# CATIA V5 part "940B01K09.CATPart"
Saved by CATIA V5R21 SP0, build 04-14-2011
Part number: 940B01K09
Bounding box of the stored display mesh (mm): x -8.5 to 199.1, y -7 to 7, z -25.901 to 9.099
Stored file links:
  C:\Users\ALI OZGUN\Desktop\alhan\940B01K09.CATPart
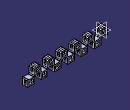
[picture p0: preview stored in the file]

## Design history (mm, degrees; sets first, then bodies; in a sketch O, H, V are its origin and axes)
Body1 (main body)
  Sketch1 on zx-plane, origin (0, 0, 0), H (-1, 0, 0), V (0, 0, 1)
    point P1 (-8.5, -8.9006)
    line L1 (-8.5, -7.9006) -> (-8, -7.4006)
    point P2 (-8, -7.4006)
    line L2 (-8, -7.4006) -> (-8, 6.6246)
    point P3 (-8, 6.6246)
    line L3 (-8, 6.6246) -> (-5.5251, 9.0994)
    point P4 (-5.5251, 9.0994)
    line L4 (-5.5251, 9.0994) -> (0, 9.0994)
    point P5 (0, 9.0994)
    line L5 (-8.5, -7.9006) -> (-8.5, -11.9006)
    point P6 (-8.5, -11.9006)
    line L6 (-8.5, -11.9006) -> (-5, -8.4006)
    point P7 (-3.5, -6.9006)
    line L7 (-5, -6.9006) -> (0, -6.9006)
    point P8 (0, -6.9006)
    line L8 (0, 6.2994) -> (-4.0825, 6.2994)
    point P9 (-4.0825, 6.2994)
    line L9 (-4.0825, 6.2994) -> (-5.2, 5.1819)
    point P10 (-5.2, 5.1819)
    line L10 (-5.2, 5.1819) -> (-5.2, -3.4006)
    point P11 (-5.2, -3.4006)
    line L11 (-5.2, -3.4006) -> (0, -3.4006)
    point P12 (0, -3.4006)
    point P13 (-8.5, -7.9006)
    point P14 (8, -7.4006)
    point P15 (8.5, -7.9006)
    line L12 (8.5, -7.9006) -> (8, -7.4006)
    point P16 (8, 6.6246)
    line L13 (8, -7.4006) -> (8, 6.6246)
    point P17 (5.5251, 9.0994)
    line L14 (8, 6.6246) -> (5.5251, 9.0994)
    point P18 (8.5, -11.9006)
    line L15 (8.5, -7.9006) -> (8.5, -11.9006)
    point P19 (3.5, -6.9006)
    line L16 (8.5, -11.9006) -> (5, -8.4006)
    point P20 (5.2, 5.1819)
    point P21 (4.0825, 6.2994)
    line L17 (4.0825, 6.2994) -> (5.2, 5.1819)
    point P22 (5.2, -3.4006)
    line L18 (5.2, 5.1819) -> (5.2, -3.4006)
    point P23 (0, -6.9006)
    line L19 (5, -6.9006) -> (0, -6.9006)
    point P24 (0, -3.4006)
    line L20 (5.2, -3.4006) -> (0, -3.4006)
    line L21 (0, 6.2994) -> (4.0825, 6.2994)
    point P25 (0, 9.0994)
    line L22 (5.5251, 9.0994) -> (0, 9.0994)
    point P26 (0, 6.2994)
    point P27 (0, 6.2994)
    line L23 (-5, -6.9006) -> (-5, -8.4006)
    line L24 (5, -6.9006) -> (5, -8.4006)
    distance L2 V = 8
    angle L3 L2 = 135
    distance L4 H = 9.0994
    distance L8 L4 = 2.8
    distance L10 L2 = 2.8
    distance L11 L7 = 3.5
    distance L9 L3 = 3
    length L3 = 3.5
    distance L4 L7 = 16
    distance L4 P6 = 21
    distance L5 L2 = 0.5
    length L5 = 4
    distance L23 L2 = 3
    vertical: L2 V, L5 V, L10 V, L23 V
    parallelism: L3 L1, L6 L1
    horizontal: L4 H, L7 H, L8 H, L11 H
    coincidence: P5 V, P8 V, P12 V, P1 L5, P26 V, P27 V, P5 P25, P8 P23, P12 P24, P26 P27, P7 L7, P7 L6, P19 L16, P19 L19
    symmetry: P2 P14 V, P13 P15 V, L1 L12 V, P3 P16 V, L2 L13 V, P4 P17 V, L3 L14 V, P6 P18 V, L5 L15 V, P7 P19 V, L6 L16 V, P10 P20 V, P9 P21 V, L9 L17 V, P11 P22 V, L10 L18 V, P8 P23 V, L7 L19 V, P12 P24 V, L11 L20 V, L8 L21 V, P5 P25 V, L4 L22 V, L23 L24 V
  Pad1: profile Sketch1, direction (0, 1, 0), length 7, mirrored extent
  Fillet1: radius 3, on edge [face of Pad1 from Sketch1.L22 | face of Pad1 from Sketch1.L14]; edge [face of Pad1 from Sketch1.L3 | face of Pad1 from Sketch1.L4]; edge [face of Pad1 from Sketch1.L2 | face of Pad1 from Sketch1.L3]; edge [face of Pad1 from Sketch1.L14 | face of Pad1 from Sketch1.L13]
  Fillet2: radius 1, on edge [face of Pad1 from Sketch1.L17 | face of Pad1 from Sketch1.L21]; edge [face of Pad1 from Sketch1.L18 | face of Pad1 from Sketch1.L17]; edge [face of Pad1 from Sketch1.L8 | face of Pad1 from Sketch1.L9]; edge [face of Pad1 from Sketch1.L9 | face of Pad1 from Sketch1.L10]
  Fillet3: radius 2, on edge [face of Pad1 from Sketch1.L23 | face of Pad1 from Sketch1.L6]; edge [face of Pad1 from Sketch1.L16 | face of Pad1 from Sketch1.L24]
  Fillet4: radius 1.5, on edge [face of Pad1 from Sketch1.L20 | face of Pad1 from Sketch1.L18]; edge [face of Pad1 from Sketch1.L10 | face of Pad1 from Sketch1.L11]
  Body2
    Sketch2 on zx-plane, origin (0, 0, 0), H (-1, 0, 0), V (0, 0, 1)
      line L1 (-8.5, -7.9006) -> (-10.5, -9.9006)
      line L2 (-10.5, -9.9006) -> (-17.3, -9.9006)
      line L3 (-8.5, -11.9006) -> (-9.05, -12.4506)
      line L4 (-9.05, -12.4506) -> (-9.05, -25.9006)
      line L5 (-9.05, -25.9006) -> (-17.3, -25.9006)
      line L6 (-17.3, -22.7006) -> (-11.85, -22.7006)
      line L7 (-11.85, -22.7006) -> (-11.85, -13.1006)
      line L8 (-11.85, -13.1006) -> (-17.3, -13.1006)
      axis line L9 (-17.3, -4.8689) -> (-17.3, -27.5881)
      point P6 (-17.3, -9.9006)
      point P7 (-17.3, -13.1006)
      point P8 (-17.3, -22.7006)
      point P9 (-17.3, -25.9006)
      reference projected line E1 (0, 9.0994) -> (-5.5251, 9.0994) from edge [face of Pad1 from Sketch1.L4 | end face of Pad1]
      reference projected line E2 (-8.5, -11.9006) -> (-5, -8.4006) from edge [face of Pad1 from Sketch1.L6 | end face of Pad1]
      reference projected line E3 (-8, -7.4006) -> (-8.5, -7.9006) from edge [face of Pad1 from Sketch1.L1 | end face of Pad1]
      projected line E4 (-8.5, -7.9006) -> (-8.5, -11.9006) from edge [face of Pad1 from Sketch1.L5 | end face of Pad1]
      projected line E5 (-8.5, -7.9006) -> (-8.5, -11.9006) from edge [face of Pad1 from Sketch1.L5 | end face of Pad1]
      reference projected line E6 (-8, 6.6246) -> (-8, -7.4006) from edge [face of Pad1 from Sketch1.L2 | end face of Pad1]
      line L10 (-17.3, -9.9006) -> (-17.3, -13.1006)
      line L11 (-17.3, -22.7006) -> (-17.3, -25.9006)
      distance L5 E1 = 35
      distance L2 L5 = 16
      distance L8 L2 = 3.2
      distance L6 L5 = 3.2
      distance L7 L4 = 2.8
      distance L4 E6 = 1.05
      distance L4 L9 = 8.25
      horizontal: L2 H, L5 H, L6 H, L8 H
      vertical: L4 V, L7 V, L9 V, L10 V, L11 V
      coincidence: P6 L9, P7 L9, P8 L9, P9 L9, L3 E2, L1 E3
    Pad2: profile Sketch2, direction (0, 1, 0), length 7, mirrored extent
    Mirror1: of the body so far, about face of Pad2 from Sketch2.L10
    Fillet5: radius 1.5, on edge [face of Pad2 | face of Mirror1] (x2); edge [face of Pad2 from Sketch2.L4 | face of Pad2]; edge [face of Mirror1 | face of Pad2] (x2); edge [face of Pad2 | face of Pad2 from Sketch2.L1]; edge [face of Pad2 from Sketch2.L7 | face of Pad2]; edge [face of Pad2 | face of Pad2 from Sketch2.L7]
  Add1: tool Body2
  RemoveFace1: RemoveFaces (face of Fillet5; face of Fillet1; face of Fillet5; face of Fillet1)
  Thickness1: Face (face of Pad2 from Sketch2.L4; face of Mirror1; face of Pad1 from Sketch1.L2; face of Pad1 from Sketch1.L13), Thickness 0.5
  RectPattern1: of the body so far, direction 1 instances 6, spacing 34.6, along edge [face of Pad1 | face of Pad2]
  Sketch3 on yz-plane, origin (0, 0, 0), H (0, 1, 0), V (0, 0, 1)
    construction line L1 (0, 4.5994) -> (0, -1.4006)
    point P1 (0, 4.5994)
    line L2 (2.5, 4.5994) -> (2.5, -1.4006)
    line L3 (-2.5, -1.4006) -> (-2.5, 4.5994)
    arc A1 centre (0, -1.4006) radius 2.5 from (2.5, -1.4006) to (-2.5, -1.4006) cw
    arc A2 centre (0, 4.5994) radius 2.5 from (-2.5, 4.5994) to (2.5, 4.5994) cw
    construction line L4 (0, -14.8006) -> (0, -20.8006)
    point P7 (0, -14.8006)
    point P8 (0, -20.8006)
    line L5 (2.5, -14.8006) -> (2.5, -20.8006)
    line L6 (-2.5, -20.8006) -> (-2.5, -14.8006)
    arc A3 centre (0, -20.8006) radius 2.5 from (2.5, -20.8006) to (-2.5, -20.8006) cw
    arc A4 centre (0, -14.8006) radius 2.5 from (-2.5, -14.8006) to (2.5, -14.8006) cw
    reference projected line E1 (-7, 9.0994) -> (7, 9.0994) from edge [face of Pad1 from Sketch1.L22 | face of Fillet1]
    distance L1 L2 = 2.5
    distance L4 L5 = 2.5
    length L1 = 6
    length L4 = 6
    distance A2 E1 = 2
    distance P8 P1 = 25.4
    coincidence: P1 V, P7 V
    vertical: L1 V, L4 V
    tangency: A1 L2, A2 L2, A1 L3, A2 L3, A3 L5, A4 L5, A3 L6, A4 L6
  Pocket1: profile Sketch3, direction (-1, 0, 0), through (limit type 3), opposite side through (limit type 3)
Body3
  Solid1: linked copy from another document
  Translate1: Direction xy-plane, Length 19.4, ToTransfor Solid1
